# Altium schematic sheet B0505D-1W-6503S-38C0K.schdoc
size 277 x 190 mm; Device: default297x210; Symbol: default297x210; Name: default297x210; Date: 2026.04.14; Rev: V1.0; Size: "A4"; Id: /; File: B0505D-1W-6503S-38C0K; Sheet: /
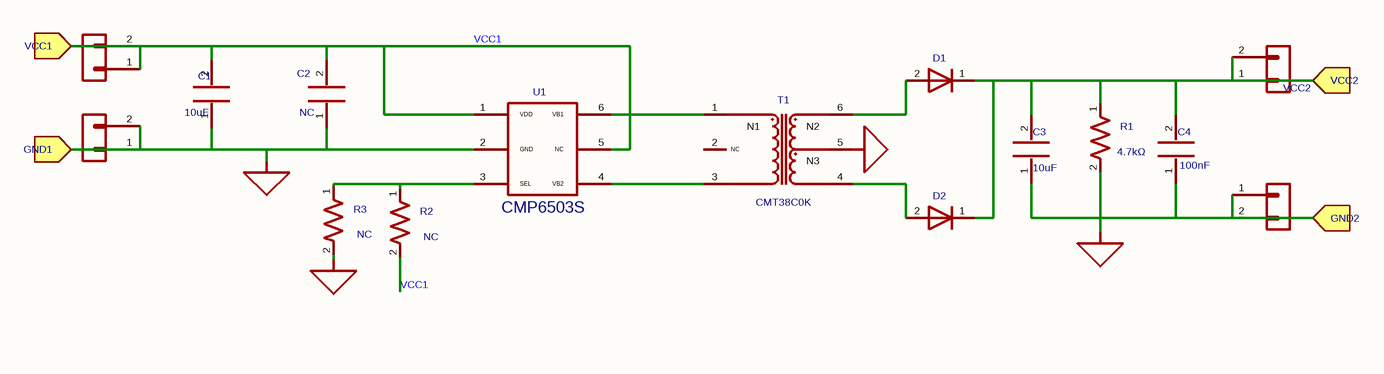
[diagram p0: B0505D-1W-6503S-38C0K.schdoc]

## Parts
C1  10uF  [MYLibrary:C0603]
C2  NC  [MYLibrary:C0603]
C3  10uF  [MYLibrary:C0603]
C4  100nF  [MYLibrary:C0603]
D1  B5819WS  [MYLibrary:SOD-123-323]  (value not drawn)
D2  B5819WS  [MYLibrary:SOD-123-323]  (value not drawn)
J2  HX PZ2.54-1x2P ZZ  [Connector_PinHeader_2.54mm:PinHeader_1x02_P2.54mm_Vertical]  (value not drawn)
J3  HX PZ2.54-1x2P ZZ  [Connector_PinHeader_2.54mm:PinHeader_1x02_P2.54mm_Vertical]  (value not drawn)
J4  HX PZ2.54-1x2P ZZ  [Connector_PinHeader_2.54mm:PinHeader_1x02_P2.54mm_Vertical]  (value not drawn)
J5  HX PZ2.54-1x2P ZZ  [Connector_PinHeader_2.54mm:PinHeader_1x02_P2.54mm_Vertical]  (value not drawn)
R1  4.7kΩ  [MYLibrary:R0603]
R2  value NC  [MYLibrary:R0603]  (hidden comment: R)
R3  value NC  [MYLibrary:R0603]  (hidden comment: R)
T1  CMT38C0K  [My Library:CMT38C0K]
U1  CMP6503S  [My Library:CMP6503S]

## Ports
GND1 (in), GND2 (in), VCC1 (in), VCC2 (in)

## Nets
GND1: C1.1 C2.1 J3.1(Pin_1) J3.2(Pin_2) R3.2 U1.2(GND) ; port GND1
GND2: C3.1 C4.1 J5.1(Pin_1) J5.2(Pin_2) R1.2 T1.5 ; port GND2
VCC1: C1.2 C2.2 J2.1(Pin_1) J2.2(Pin_2) R2.2 U1.1(VDD) U1.5(NC) ; port VCC1
VCC2: C3.2 C4.2 D1.1(K) D2.1(K) J4.1(Pin_1) J4.2(Pin_2) R1.1 ; port VCC2
NetD1_2: D1.2(A) T1.6
NetD2_2: D2.2(A) T1.4
NetR2_1: R2.1 R3.1 U1.3(SEL)
NetT1_1: T1.1 U1.6(VB1)
NetT1_3: T1.3 U1.4(VB2)

Not connected (* = marked no-connect by the designer): T1 2

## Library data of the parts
C1 = 0603X106K100NT: 容值:10uF;精度:±10%;额定电压:10V;温度系数:X5R;; Manufacturer: FH(风华); Symbol: My_Library_C; Add into BOM: yes; 3D Model: ac125912035d415993ca9572d50418b1; 3D Model Transform: 62.992,31.496,0,0,0,0,0,0,0; Tolerance: ±10%; Voltage Rating: 10V; Temperature Coefficient: X5R; ki_keywords: cap capacitor; ki_fp_filters: C_*; UniqueId: 5fb4f22ffcb6a001; ModelName: C0603_L1.6-W0.8-H0.8
C2 = CC0603KRX7R9BB104: 容值:100nF;精度:±10%;额定电压:50V;温度系数:X7R;; Manufacturer: YAGEO(国巨); Symbol: My_Library_C; Add into BOM: no; Convert to PCB: yes; 3D Model: ac125912035d415993ca9572d50418b1; 3D Model Transform: 62.992,31.496,0,0,0,0,0,0,0; Tolerance: ±10%; Voltage Rating: 50V; Temperature Coefficient: X7R; ki_keywords: cap capacitor; ki_fp_filters: C_*; UniqueId: 21d50210554cb61f; ModelName: C0603_L1.6-W0.8-H0.8
C3 = 0603X106K100NT: 容值:10uF;精度:±10%;额定电压:10V;温度系数:X5R;; Manufacturer: FH(风华); Symbol: My_Library_C; Add into BOM: yes; 3D Model: ac125912035d415993ca9572d50418b1; 3D Model Transform: 62.992,31.496,0,0,0,0,0,0,0; Tolerance: ±10%; Voltage Rating: 10V; Temperature Coefficient: X5R; ki_keywords: cap capacitor; ki_fp_filters: C_*; UniqueId: ec64484c8c07847f; ModelName: C0603_L1.6-W0.8-H0.8
C4 = CC0603KRX7R9BB104: 容值:100nF;精度:±10%;额定电压:50V;温度系数:X7R;; Manufacturer: YAGEO(国巨); Symbol: My_Library_C; Add into BOM: yes; 3D Model: ac125912035d415993ca9572d50418b1; 3D Model Transform: 62.992,31.496,0,0,0,0,0,0,0; Tolerance: ±10%; Voltage Rating: 50V; Temperature Coefficient: X7R; ki_keywords: cap capacitor; ki_fp_filters: C_*; UniqueId: 623e2bb2442f04df; ModelName: C0603_L1.6-W0.8-H0.8
D1 = B5819WS_C64886: 二极管配置:独立式;正向压降(Vf):900mV@3A;直流反向耐压(Vr):40V;整流电流:1A;; Manufacturer: MDD(辰达半导体); Symbol: My_Library_D; Add into BOM: yes; 3D Model: db63db13d9e342eb939127d413d6200b; 3D Model Transform: 104.3305,51.181,0,0,0,0,0,-0.004,0; Diode Configuration: 独立式; Voltage - DC Reverse(Vr): 40V; Current - Rectified: 1A; Reverse Leakage Current (Ir): 1mA@40V; Operating Junction Temperature Range: -55℃~+125℃; Non-Repetitive Peak Forward Surge Current: 25A; Value: D; ki_keywords: diode; ki_fp_filters: TO-???* *_Diode_* *SingleDiode* D_*; UniqueId: 07a0d5848cd81316; ModelName: SOD-323_L1.8-W1.3-LS2.5-RD
D2 = B5819WS_C64886: 二极管配置:独立式;正向压降(Vf):900mV@3A;直流反向耐压(Vr):40V;整流电流:1A;; Manufacturer: MDD(辰达半导体); Symbol: My_Library_D; Add into BOM: yes; 3D Model: db63db13d9e342eb939127d413d6200b; 3D Model Transform: 104.3305,51.181,0,0,0,0,0,-0.004,0; Diode Configuration: 独立式; Voltage - DC Reverse(Vr): 40V; Current - Rectified: 1A; Reverse Leakage Current (Ir): 1mA@40V; Operating Junction Temperature Range: -55℃~+125℃; Non-Repetitive Peak Forward Surge Current: 25A; Value: D; ki_keywords: diode; ki_fp_filters: TO-???* *_Diode_* *SingleDiode* D_*; UniqueId: fa5cd661465da5bc; ModelName: SOD-323_L1.8-W1.3-LS2.5-RD
J2 = HX PZ2.54-1x2P ZZ: 插针结构:1x2P;间距:2.54mm;行距:-;圆针/方针:方针;安装方式:直插;排数:单排;总PIN位数:2P;额定电流:3A;额定电压:1kV;配合针长度:6mm;塑高:2.5mm;端接针长度:3mm;触头材质:黄铜;触头镀层:金;工作温度:-40℃~+105℃;颜色:黑色;; Manufacturer: hanxia(韩下); Symbol: Connector_Generic_Conn_01x02; Add into BOM: yes; 3D Model: c7a9f3c3e6e34627af2bf939e464cb35; 3D Model Transform: 200,100,0,0,0,0,0,0,-118.11; Pin Structure: 1x2P; Pitch: 2.54mm; Circluar Pins/Square Pins: 方针; Current Rating: 3A; Voltage Rating (Max): 1kV; ki_keywords: connector; ki_fp_filters: Connector*:*_1x??_*; UniqueId: 42913bc3a3449998; ModelName: HDR-TH_2P-P2.54-M-LI-1X2P
J3 = HX PZ2.54-1x2P ZZ: 插针结构:1x2P;间距:2.54mm;行距:-;圆针/方针:方针;安装方式:直插;排数:单排;总PIN位数:2P;额定电流:3A;额定电压:1kV;配合针长度:6mm;塑高:2.5mm;端接针长度:3mm;触头材质:黄铜;触头镀层:金;工作温度:-40℃~+105℃;颜色:黑色;; Manufacturer: hanxia(韩下); Symbol: Connector_Generic_Conn_01x02; Add into BOM: yes; 3D Model: c7a9f3c3e6e34627af2bf939e464cb35; 3D Model Transform: 200,100,0,0,0,0,0,0,-118.11; Pin Structure: 1x2P; Pitch: 2.54mm; Circluar Pins/Square Pins: 方针; Current Rating: 3A; Voltage Rating (Max): 1kV; ki_keywords: connector; ki_fp_filters: Connector*:*_1x??_*; UniqueId: 6ca7fcf0d18ad80e; ModelName: HDR-TH_2P-P2.54-M-LI-1X2P
J4 = HX PZ2.54-1x2P ZZ: 插针结构:1x2P;间距:2.54mm;行距:-;圆针/方针:方针;安装方式:直插;排数:单排;总PIN位数:2P;额定电流:3A;额定电压:1kV;配合针长度:6mm;塑高:2.5mm;端接针长度:3mm;触头材质:黄铜;触头镀层:金;工作温度:-40℃~+105℃;颜色:黑色;; Manufacturer: hanxia(韩下); Symbol: Connector_Generic_Conn_01x02; Add into BOM: yes; 3D Model: c7a9f3c3e6e34627af2bf939e464cb35; 3D Model Transform: 200,100,0,0,0,0,0,0,-118.11; Pin Structure: 1x2P; Pitch: 2.54mm; Circluar Pins/Square Pins: 方针; Current Rating: 3A; Voltage Rating (Max): 1kV; ki_keywords: connector; ki_fp_filters: Connector*:*_1x??_*; UniqueId: 048fde32f53a6793; ModelName: HDR-TH_2P-P2.54-M-LI-1X2P
J5 = HX PZ2.54-1x2P ZZ: 插针结构:1x2P;间距:2.54mm;行距:-;圆针/方针:方针;安装方式:直插;排数:单排;总PIN位数:2P;额定电流:3A;额定电压:1kV;配合针长度:6mm;塑高:2.5mm;端接针长度:3mm;触头材质:黄铜;触头镀层:金;工作温度:-40℃~+105℃;颜色:黑色;; Manufacturer: hanxia(韩下); Symbol: Connector_Generic_Conn_01x02; Add into BOM: yes; 3D Model: c7a9f3c3e6e34627af2bf939e464cb35; 3D Model Transform: 200,100,0,0,0,0,0,0,-118.11; Pin Structure: 1x2P; Pitch: 2.54mm; Circluar Pins/Square Pins: 方针; Current Rating: 3A; Voltage Rating (Max): 1kV; ki_keywords: connector; ki_fp_filters: Connector*:*_1x??_*; UniqueId: c38aec87e6867e62; ModelName: HDR-TH_2P-P2.54-M-LI-1X2P
R1 = RC0603FR-074K7L: 电阻类型:厚膜电阻;阻值:4.7kΩ;精度:±1%;功率:100mW;工作电压:75V;温度系数:±100ppm/℃;; Manufacturer: YAGEO(国巨); Symbol: My_Library_R; Add into BOM: yes; 3D Model: fc143cca1e79419f9cd78b61e9279f08; 3D Model Transform: 31.8897,63.7794,0,90,0,0,0,0,0; Tolerance: ±1%; Power(Watts): 100mW; Voltage-Supply(Max): 75V; ki_keywords: R res resistor; ki_fp_filters: R_*; UniqueId: 4e166b190d4de1c3; ModelName: R0603
R2 = My_Library_R: Add into BOM: no; ki_keywords: R res resistor; ki_fp_filters: R_*; UniqueId: 06442d24ab060343
R3 = My_Library_R: Add into BOM: no; ki_keywords: R res resistor; ki_fp_filters: R_*; UniqueId: 6e26aea592918673
T1 = Library_CMT3990K: UniqueId: cf2c480e5945250c; Attribute1: T1; AddInBom: yes
U1 = CMP6503S: CMP6503S 是低噪声、低 EMI 辐射的全桥式隔离电源变压器驱动器，特别适合于小型化的隔离电源方案，属于 线 易 ChipMate(CM) 系 列 的 电 源 解 决 方 案 。CMP6503S 内 部 集 成 两 对 N 型 和 P 型 功 率MOSFET，通过芯片内部集成振荡器提供具有精准时序和死区时间的互补驱动信号。驱动器芯片 CMP6503S和变压器配合必要的容阻和整流二极管，可以实现5.0V 输入/5.0V 输出的 200 mA 隔离非稳压电源；或者 3.3V 输入/3.3V 输出的 10; Manufacturer: coileasy(线易); Symbol: MyLibrary_CMP6503; Add into BOM: yes; 3D Model: 7ba65df16e7b4570af156e925f9c37fe; 3D Model Transform: 114.173,114.173,0,90,0,0,0,0,0; Input Voltage: 3V~5.5V; Quiescent Current: 2.2mA; UniqueId: 48a4a086d8c42a18; ModelName: SOT-23-5_L2.9-W1.6-P0.95-LS2.8-BR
